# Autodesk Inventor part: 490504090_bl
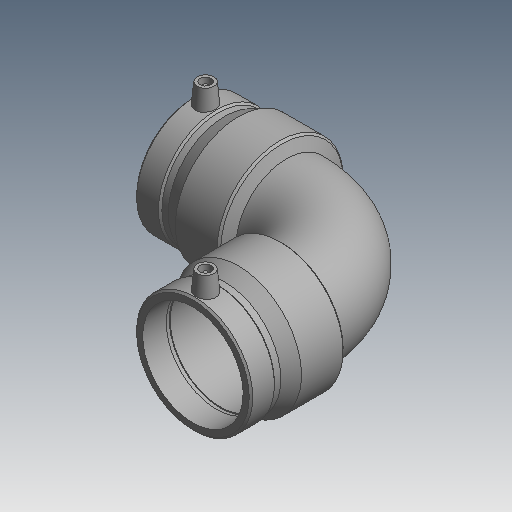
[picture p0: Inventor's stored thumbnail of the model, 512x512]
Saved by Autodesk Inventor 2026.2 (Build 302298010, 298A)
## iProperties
Created: 2017-06
Part Number: 490504090_bl
Material: Generic
Description: PLASSON 90° ELBOW 90
Document SubType Name: Modeling
Designer: KIM
Mass: 55.0731 g
Surface Area: 148.067 cm^2
Volume: 55.0731 cm^3
Density: 1 g/cm^3
Appearance: Default
Author: KIM
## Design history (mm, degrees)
derived "490504.ipt"
feature "Solid1::490504.ipt" dims "ScaleForDerivedMember" = 10
tag "TaggingFeature1"
body "Solid1"
other parameters: "d2" = 113 [user parameter], "d4" = 53.25 [user parameter], "d5" = 101.7 [user parameter], "d8" = 168 deg [user parameter], "d10" = 31.2 [user parameter], "d11" = 10.4 [user parameter], "d14" = 17.6296 [user parameter], "d19" = 3.52592 [user parameter], "d20" = 168 deg [user parameter], "d22" = 103.96 [user parameter], "d23" = 113 [user parameter], "d24" = 100.8412 [user parameter], "d29" = 69 [user parameter], "d30" = 15 [user parameter], "d31" = 74.55 [user parameter], "d34" = 5 deg [user parameter], "d35" = 15 [user parameter], "d39" = 5 deg [user parameter], "d41" = 4 [user parameter], "d42" = 14 [user parameter], "d43" = 0 [user parameter], "d45" = 4 [user parameter], "d46" = 14 [user parameter], "d47" = 0 [user parameter], "d50" = 76.5 [user parameter], "d51" = 31.2 [user parameter], "d52" = 78 [user parameter], "d54" = 90 deg [user parameter], "d67" = 45 deg [user parameter], "d71" = 90 deg [user parameter], "d75" = 5.65 [user parameter], "d82" = 45 deg [user parameter], "d83" = 78 [user parameter], "d84" = 101.7 [user parameter], "d87" = 90 deg [user parameter], "d90" = 78 [user parameter], "d91" = 0 [user parameter], "d92" = 78 [user parameter], "d93" = 0 [user parameter], "d94" = 90 deg [user parameter], "d101" = 3 [user parameter], "d102" = 0 [user parameter], "d103" = 3 [user parameter], "d104" = 0 [user parameter], "d105" = 22.62 [user parameter], "d106" = 5.655 [user parameter], "d110" = 42.9 [user parameter], "d111" = 213 [user parameter], "d112" = 213 [user parameter], "d113" = 213 [user parameter], "d114" = 213 [user parameter], "L_" = 213 [user parameter], "L_1" = 78 [user parameter], "D_" = 113 [user parameter], "A_" = 69 [user parameter], "d_2" = 12 [user parameter]
